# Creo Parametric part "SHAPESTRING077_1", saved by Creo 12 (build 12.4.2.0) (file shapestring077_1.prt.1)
Units: Custom; MM, KILOGRAM, SECS

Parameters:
  PTC_WM_ITERATION = "0"
  PTC_WM_VERSION = "-.0"
  PTC_WM_LIFECYCLE_STATE = "In Work"
  PTC_WM_LIFECYCLE = "MO_CADDocument"
  PTC_WM_CREATED_BY = "Maximilian Roepper (Z0017RMS: MO)"
  PTC_WM_CREATED_ON = "18-Sep-26 11:36:42 AM"
  PTC_WM_MODIFIED_BY = "Maximilian Roepper (Z0017RMS: MO)"
  PTC_WM_MODIFIED_ON = "18-Sep-26 11:36:46 AM"
  PDMLINKNUMBER = "PDM000071455129"
  PTC_WM_NAME = "shapestring077_1.prt"
  PTC_WM_NUMBER = "PDM000071455129"

Other parameters: WEIGHT, WEIGHT_FACTOR, WEIGHT_ADD, _MASS_TEMP, _DIFF_TEMP, MC_ERRORS, SUPPLIER

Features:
  1. coordinate system
  2. datum plane "PRT_YZ"
  3. datum plane "PRT_XY"
  4. datum plane "PRT_XZ"
  5. coordinate system
  6. datum axis
  7. datum axis
  8. datum axis
  9. coordinate system
  10. imported feature
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
Other named items: PRT, SIEMENS_MO, DRW_VIEW_ORG, PRT_X, PRT_Y, PRT_Z, CS0, ROUGH_GROB

Layers: 00_STD_CSYS-KSYS, 01_STD_PLANES-EBENEN, 02_STD_AXES-ACHSEN, 03_STD_CSYS-KSYS, 24_IMPORT_FEAT-IMPORT_KE, INTFCLR

Surfaces: 1 plane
